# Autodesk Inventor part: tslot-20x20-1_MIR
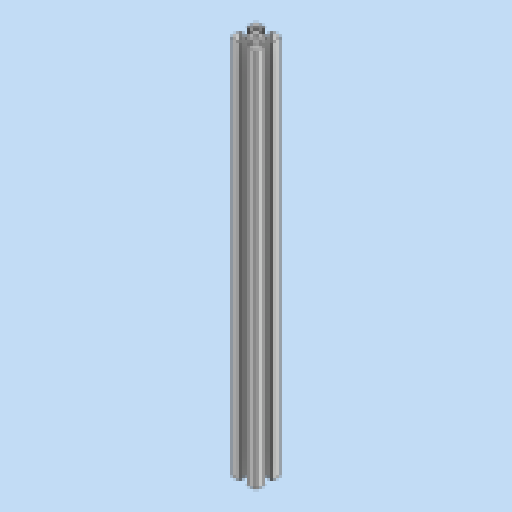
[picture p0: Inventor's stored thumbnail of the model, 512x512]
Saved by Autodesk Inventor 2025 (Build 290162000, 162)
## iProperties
Created: 2025-03
Part Number: tslot-20x20-1_MIR
Material: Generico
Document SubType Name: Modeling
Designer: R5800u
Density: 1 g/cm^3
Appearance: Default
Author: Ryzen5700u
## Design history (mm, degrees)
derived "tslot-20x20-1.ipt"
  sketch "Schizzo1"
    geometry: L1 (-3.761, -16)-(-4.7, -16) reference; L2 (-3.761, -16)-(-0.7, -12.939) reference; L3 (-0.7, -12.939)-(-0.7, -10.52) reference; L4 (-0.4, -10)-(-0.7, -10.52) reference; L5 (-0.4, -10)-(-0.7, -9.48) reference; L6 (-0.7, -7.061)-(-0.7, -9.48) reference; L7 (-3.761, -4)-(-0.7, -7.061) reference; L8 (-3.761, -4)-(-4.7, -4) reference; L9 (-4.7, -4)-(-4.7, -7) reference; L10 (-4.7, -7)-(-6.4, -7) reference; L11 (-6.7, -6.7)-(-6.7, -1) reference; L12 (-5.7, 0)-(0, 0) reference; L13 (0.3, -2)-(0.3, -0.3) reference; L14 (-2.7, -2)-(0.3, -2) reference; L15 (-2.7, -2.939)-(-2.7, -2) reference; L16 (-2.7, -2.939)-(0.361, -6) reference; L17 (0.361, -6)-(2.78, -6) reference; L18 (3.3, -6.3)-(2.78, -6) reference; L19 (3.3, -6.3)-(3.82, -6) reference; L20 (6.239, -6)-(3.82, -6) reference; L21 (9.3, -2.939)-(6.239, -6) reference; L22 (9.3, -2.939)-(9.3, -2) reference; L23 (9.3, -2)-(6.3, -2) reference; L24 (6.3, -2)-(6.3, -0.3) reference; L25 (12.3, 0)-(6.6, 0) reference; L26 (13.3, -6.7)-(13.3, -1) reference; L27 (11.3, -7)-(13, -7) reference; L28 (11.3, -4)-(11.3, -7) reference; L29 (10.361, -4)-(11.3, -4) reference; L30 (10.361, -4)-(7.3, -7.061) reference; L31 (7.3, -7.061)-(7.3, -9.48) reference; L32 (7, -10)-(7.3, -9.48) reference; L33 (7, -10)-(7.3, -10.52) reference; L34 (7.3, -12.939)-(7.3, -10.52) reference; L35 (10.361, -16)-(7.3, -12.939) reference; L36 (10.361, -16)-(11.3, -16) reference; L37 (11.3, -16)-(11.3, -13) reference; L38 (11.3, -13)-(13, -13) reference; L39 (13.3, -13.3)-(13.3, -19) reference; L40 (12.3, -20)-(6.6, -20) reference; L41 (6.3, -18)-(6.3, -19.7) reference; L42 (9.3, -18)-(6.3, -18) reference; L43 (9.3, -17.061)-(9.3, -18) reference; L44 (9.3, -17.061)-(6.239, -14) reference; L45 (6.239, -14)-(3.82, -14) reference; L46 (3.3, -13.7)-(3.82, -14) reference; L47 (3.3, -13.7)-(2.78, -14) reference; L48 (0.361, -14)-(2.78, -14) reference; L49 (-2.7, -17.061)-(0.361, -14) reference; L50 (-2.7, -17.061)-(-2.7, -18) reference; L51 (-2.7, -18)-(0.3, -18) reference; L52 (0.3, -18)-(0.3, -19.7) reference; L53 (-5.7, -20)-(0, -20) reference; L54 (-6.7, -13.3)-(-6.7, -19) reference; L55 (-4.7, -13)-(-6.4, -13) reference; L56 (-4.7, -16)-(-4.7, -13) reference; C1 r 2.1 at (3.3, -10) reference; A1 r 0.3 centre (-6.4, -6.7) between (-6.7, -6.7) and (-6.4, -7) reference; A2 r 1 centre (-5.7, -1) between (-5.7, 0) and (-6.7, -1) reference; A3 r 0.3 centre (0, -0.3) between (0.3, -0.3) and (0, 0) reference; A4 r 0.3 centre (6.6, -0.3) between (6.6, 0) and (6.3, -0.3) reference; A5 r 1 centre (12.3, -1) between (13.3, -1) and (12.3, 0) reference; A6 r 0.3 centre (13, -6.7) between (13, -7) and (13.3, -6.7) reference; A7 r 0.3 centre (13, -13.3) between (13.3, -13.3) and (13, -13) reference; A8 r 1 centre (12.3, -19) between (12.3, -20) and (13.3, -19) reference; A9 r 0.3 centre (6.6, -19.7) between (6.3, -19.7) and (6.6, -20) reference; A10 r 0.3 centre (0, -19.7) between (0, -20) and (0.3, -19.7) reference; A11 r 1 centre (-5.7, -19) between (-6.7, -19) and (-5.7, -20) reference; A12 r 0.3 centre (-6.4, -13.3) between (-6.4, -13) and (-6.7, -13.3) reference; 1 further point
feature "Solido1::tslot-20x20-1.ipt" dims "d0" = 10
tag "Lavorazione contrassegno1"
node "Solido1"
